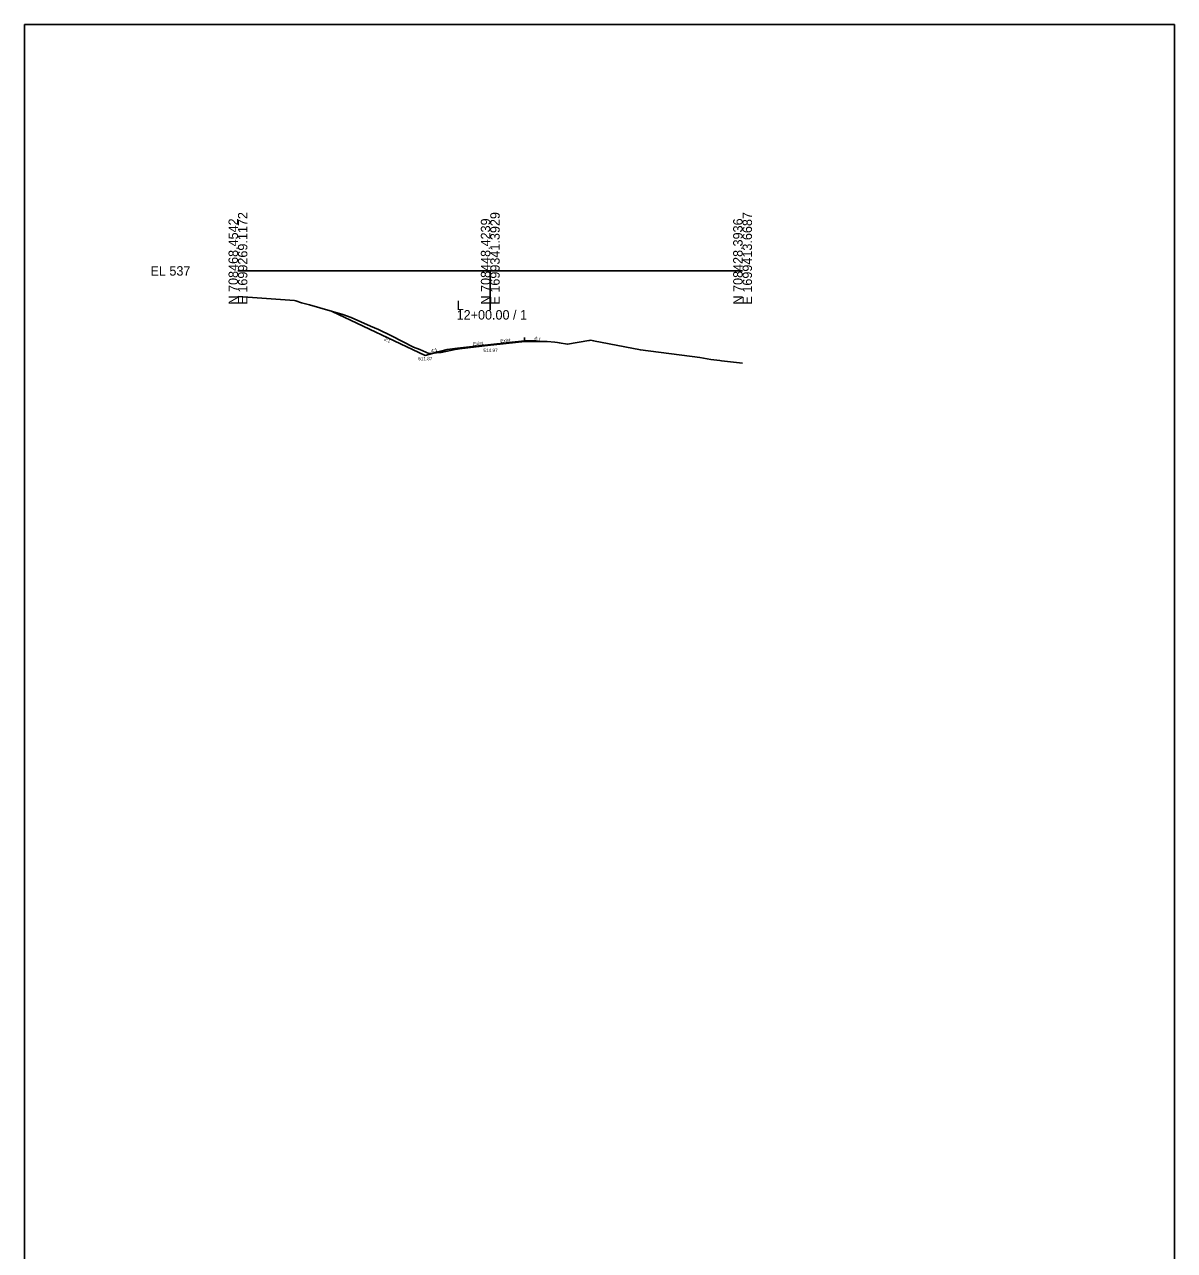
# Model space of a CAD drawing. Extents: x -63 to 1153, y -24 to 9522.
# Drawn here: x -63.4 to 278.4, y 1208.9 to 1573.2 of the extents above; entities that cross this region are included whole.
import ezdxf

# ---------------------------------------------------------------- set-up
doc = ezdxf.new("R2010")
doc.units = 0
for name, color, linetype in [('Default', 7, 'Continuous'), ('Exist Cross Section Cell', 7, 'Continuous'), ('Exist XS Center Line Elevation Label', 7, 'Continuous'), ('Exist XS Ground Line', 7, 'Continuous'), ('Prop CMT DNC', 7, 'Continuous'), ('Prop CMT Pvmt Surface Overlay', 7, 'Continuous'), ('Prop CMT Slope Grass', 7, 'Continuous'), ('Prop XS Ditch Standard Text', 7, 'Continuous'), ('Prop XS Earthwork Shape', 7, 'Continuous'), ('Prop XS EOT Tick Mark', 7, 'Continuous'), ('Prop XS SE Text', 7, 'Continuous'), ('Prop XS Side Slope Text', 7, 'Continuous')]:
    doc.layers.add(name, color=color, linetype=linetype)

msp = doc.modelspace()

# ---------------------------------------------------------------- linework, layer by layer
at = {"layer": 'Exist Cross Section Cell'}
for p, q in [((0, 1500), (75, 1500)), ((75, 1500), (150, 1500)), ((75, 1500), (75, 1488.34))]:
    msp.add_line(p, q, dxfattribs=at)
at = {"layer": 'Exist XS Ground Line'}
msp.add_lwpolyline([(0, 1492.45), (0.09, 1492.44), (4.36, 1492.09), (9.85, 1491.75), (16.83, 1491.2), (17.25, 1491.12), (18.93, 1490.53), (21.25, 1489.87), (31.16, 1487), (33.63, 1486.11), (39.42, 1483.61), (41.77, 1482.56), (45.6, 1480.73), (48.9, 1478.99), (52.19, 1477.35), (54.04, 1476.65), (56.73, 1475.41), (60.13, 1475.74), (60.41, 1475.79), (64.56, 1476.66), (65.1, 1476.74), (65.88, 1476.83), (75, 1477.97), (75.2, 1478), (76.06, 1478.08), (85.23, 1478.99), (86.62, 1479), (91.89, 1479.05), (94.23, 1478.82), (94.99, 1478.74), (95.52, 1478.66), (97.93, 1478.2), (104.3, 1479.29), (104.54, 1479.32), (104.89, 1479.38), (105.7, 1479.23), (119.65, 1476.53), (137.34, 1474.25), (140.59, 1473.7), (143.19, 1473.39), (143.74, 1473.29), (150, 1472.58)], dxfattribs=at)
at = {"layer": 'Prop CMT DNC'}
msp.add_lwpolyline([(-63.45, 1573.23), (278.38, 1573.23), (278.38, 844.51), (-63.45, 844.51)], close=True, dxfattribs=at)
at = {"layer": 'Prop CMT Pvmt Surface Overlay'}
for points in [[(75.2, 1478.14), (65.23, 1477.02)], [(75.2, 1478.14), (85.19, 1479.22)]]:
    msp.add_lwpolyline(points, dxfattribs=at)
at = {"layer": 'Prop CMT Slope Grass'}
for p, q in [((88.18, 1479.36), (89.54, 1479.02)), ((62.23, 1476.68), (55.6, 1474.87)), ((65.22, 1477.02), (65.22, 1476.75)), ((85.2, 1479.22), (85.2, 1478.99))]:
    msp.add_line(p, q, dxfattribs=at)
for points in [[(27.99, 1487.92), (55.6, 1474.87)], [(85.2, 1479.22), (88.18, 1479.36)], [(65.22, 1477.02), (62.23, 1476.68)]]:
    msp.add_lwpolyline(points, dxfattribs=at)
at = {"layer": 'Prop XS Earthwork Shape'}
for points in [[(58.04, 1475.54), (55.6, 1474.87), (27.99, 1487.92), (31.16, 1487), (33.63, 1486.11), (39.42, 1483.61), (41.77, 1482.56), (45.6, 1480.73), (48.9, 1478.99), (52.19, 1477.35), (54.04, 1476.65), (56.73, 1475.41)], [(85.2, 1479.22), (88.18, 1479.36), (89.54, 1479.02), (86.62, 1479), (85.23, 1478.99), (85.2, 1478.99)], [(65.1, 1476.74), (65.22, 1476.75), (65.22, 1477.02), (62.23, 1476.68), (58.04, 1475.54), (60.13, 1475.74), (60.41, 1475.79), (64.56, 1476.66)]]:
    msp.add_lwpolyline(points, close=True, dxfattribs=at)
at = {"layer": 'Prop XS EOT Tick Mark'}
msp.add_lwpolyline([(85.19, 1479.22), (85.17, 1480.22)], dxfattribs=at)

# ---------------------------------------------------------------- texts
at = {"layer": 'Default'}
msp.add_text('-', height=0.0001, dxfattribs=at).set_placement((0, 1500))
msp.add_text('-', height=0.0001, dxfattribs=at).set_placement((0, 1500))
at = {"layer": 'Exist Cross Section Cell'}
for s, p in [('E 1699269.1172', (2.8, 1490)), ('E 1699341.3929', (77.8, 1490)), ('E 1699413.6687', (152.8, 1490)), ('N 708468.4542', (0, 1490)), ('N 708448.4239', (75, 1490)), ('N 708428.3936', (150, 1490))]:
    msp.add_text(s, height=2.8, rotation=90, dxfattribs=at).set_placement(p)
for s, p in [('EL 537', (-26, 1498.6)), ('L', (65, 1488.34)), ('12+00.00 / 1', (65, 1485.54))]:
    msp.add_text(s, height=2.8, dxfattribs=at).set_placement(p)
at = {"layer": 'Exist XS Center Line Elevation Label'}
msp.add_text('514.97', height=1, dxfattribs=at).set_placement((72.97, 1475.87))
at = {"layer": 'Prop XS Ditch Standard Text'}
msp.add_text('511.87', height=1, dxfattribs=at).set_placement((53.57, 1473.46))
at = {"layer": 'Prop XS SE Text'}
for p in [(78.05, 1478.69), (69.9, 1477.76)]:
    msp.add_text('Exist.', height=1, rotation=6.4909, dxfattribs=at).set_placement(p)
at = {"layer": 'Prop XS Side Slope Text'}
for s, rotation, p in [('2:1', 333.4327, (43.35, 1479.47)), ('4:1', 340.5124, (88.03, 1479.69)), ('4:1', 14.0362, (57.51, 1475.69))]:
    msp.add_text(s, height=1, rotation=rotation, dxfattribs=at).set_placement(p)

doc.saveas('drawing.dxf')
